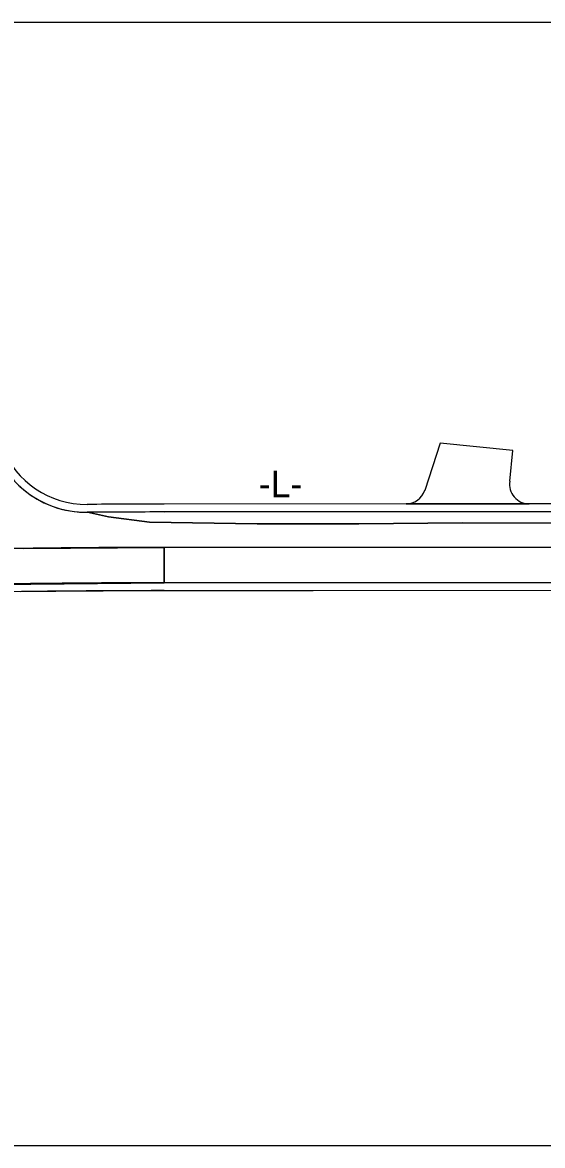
# Model space of a CAD drawing. Extents: x 2110629 to 2114002, y 669321 to 671542.
# Drawn here: x 2111515 to 2111780, y 670218 to 670789 of the extents above; entities that cross this region are included whole.
import ezdxf

# ---------------------------------------------------------------- set-up
doc = ezdxf.new("R2010")
doc.units = 0
doc.layers.add('Default Symbol Cogo Number', color=7, linetype='Continuous')
doc.layers.add('Exist Roads Soil', color=7, linetype='Continuous')

msp = doc.modelspace()

# ---------------------------------------------------------------- linework, layer by layer
at = {"layer": 'Default Symbol Cogo Number'}
msp.add_lwpolyline([(2112405.47, 670789.4), (2111041.56, 670789.4), (2111041.56, 670218.3), (2112405.47, 670218.3)], close=True, dxfattribs=at)
at = {"layer": 'Exist Roads Soil'}
for p, q in [((2111727.86, 670575.54), (2111720.04, 670551.48)), ((2111764.89, 670571.73), (2111727.86, 670575.54)), ((2111763.29, 670556.12), (2111764.89, 670571.73)), ((2111710.54, 670544.58), (2111587.56, 670544.48)), ((2111710.54, 670544.58), (2111773.18, 670544.63)), ((2111773.18, 670544.63), (2111710.54, 670544.58)), ((2111922.27, 670544.75), (2111773.18, 670544.63)), ((2111587.56, 670540.48), (2111922.27, 670540.75)), ((2111922.27, 670540.75), (2111587.56, 670540.48)), ((2111516.22, 670521.98), (2111587.58, 670522.48)), ((2111587.58, 670522.48), (2111516.22, 670521.98)), ((2111827.05, 670522.67), (2111587.58, 670522.48)), ((2111587.58, 670522.48), (2111827.05, 670522.67)), ((2111587.58, 670522.48), (2111587.59, 670504.48)), ((2111587.59, 670504.48), (2111587.58, 670522.48)), ((2111435.69, 670502.75), (2111587.59, 670504.48)), ((2112111.14, 670504.9), (2111587.59, 670504.48)), ((2111587.59, 670504.48), (2111827.07, 670504.67)), ((2111514.49, 670499.96), (2111532.38, 670500.17)), ((2111532.38, 670500.17), (2111556.55, 670500.37)), ((2111556.55, 670500.37), (2111578.34, 670500.47)), ((2111578.34, 670500.47), (2111596.03, 670500.49)), ((2111587.59, 670500.48), (2111596.03, 670500.49)), ((2111596.03, 670500.49), (2111618.38, 670500.5)), ((2111596.03, 670500.49), (2111618.38, 670500.5)), ((2111618.38, 670500.5), (2111638.61, 670500.52)), ((2111618.38, 670500.5), (2111638.61, 670500.52)), ((2111638.61, 670500.52), (2111663.34, 670500.54)), ((2111663.34, 670500.54), (2111795.92, 670500.65))]:
    msp.add_line(p, q, dxfattribs=at)
for points in [[(2111954.08, 670566.84), (2111954.01, 670566.54), (2111941.68, 670542.28), (2111923.48, 670535.07), (2111887.51, 670534.56), (2111839.53, 670534.71), (2111790.25, 670534.72), (2111739.32, 670534.92), (2111686.56, 670534.47), (2111634.88, 670534.45), (2111580.02, 670535.22), (2111559.25, 670538.03), (2111548.57, 670540.32)], [(2111515.76, 670552.07), (2111515.64, 670552.13), (2111515.46, 670552.32)], [(2111548.57, 670540.32), (2111559.25, 670538.03), (2111580.02, 670535.22), (2111634.88, 670534.45)], [(2111634.88, 670534.45), (2111686.56, 670534.47), (2111739.32, 670534.92), (2111790.25, 670534.72), (2111839.53, 670534.71), (2111887.51, 670534.56), (2111923.48, 670535.07), (2111941.68, 670542.28)], [(2111638.61, 670500.52), (2111663.34, 670500.54), (2111795.92, 670500.65)]]:
    msp.add_lwpolyline(points, dxfattribs=at)
for centre, radius, start, end in [((2111547.96, 670590.31), 46, 201.3689, 270.4354), ((2111547.96, 670590.31), 50, 201.3689, 270.4354), ((2111547.96, 670590.31), 50, 216.8192, 229.4581), ((2111773.17, 670554.63), 10, 171.4174, 270.0458), ((2111547.96, 670590.31), 50, 229.9036, 270.4354), ((2111710.53, 670554.58), 10, 270.0458, 341.9812), ((2111592.18, 664771.15), 5773.33, 90.045845, 90.43536), ((2111592.18, 664771.15), 5769.33, 90.045845, 90.43536), ((2111592.18, 664771.15), 5769.33, 90.433083, 90.43536), ((2111592.18, 664771.15), 5769.33, 90.045845, 90.433083), ((2111592.18, 664771.15), 5751.33, 90.045845, 91.563897), ((2111592.18, 664771.15), 5751.33, 90.756767, 91.563897), ((2111592.18, 664771.15), 5733.33, 90.045845, 91.324788), ((2111592.18, 664771.15), 5733.33, 90.045845, 91.262159), ((2111592.18, 664771.15), 5729.33, 90.04584, 91.10331)]:
    msp.add_arc(centre, radius, start, end, dxfattribs=at)

# ---------------------------------------------------------------- texts
at = {"layer": 'Default Symbol Cogo Number'}
msp.add_text('-L-', height=13.5, rotation=360, dxfattribs=at).set_placement((2111635.71, 670547.98))

doc.saveas('drawing.dxf')
